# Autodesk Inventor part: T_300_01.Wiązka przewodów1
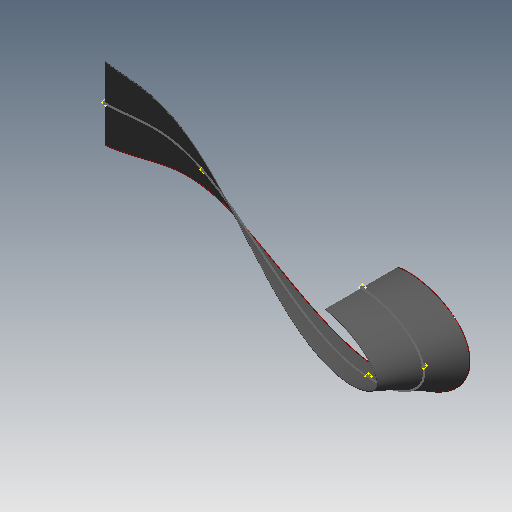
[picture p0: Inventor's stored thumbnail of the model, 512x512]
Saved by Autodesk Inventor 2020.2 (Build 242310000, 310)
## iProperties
Created: 2014-09
Part Number: T_300_01.Wiązka przewodów1
Material: Ogólne
Document SubType Name: Modelowanie
Designer: F.Stasiak
Appearance: Ogólne
Catalog Web Link: www.expertbooks.pl
Manager: www.cadconsulting.pl
Company: Fabian Stasiak CAD Consulting
Author: F.Stasiak
Subject: Zbiór ćwiczeń. Autodesk Inventor 2020. Kurs Professional
## Parameters: d64 = 0, d65 = 0, d66 = 0, d67 = 0, d68 = 0, d69 = 0
